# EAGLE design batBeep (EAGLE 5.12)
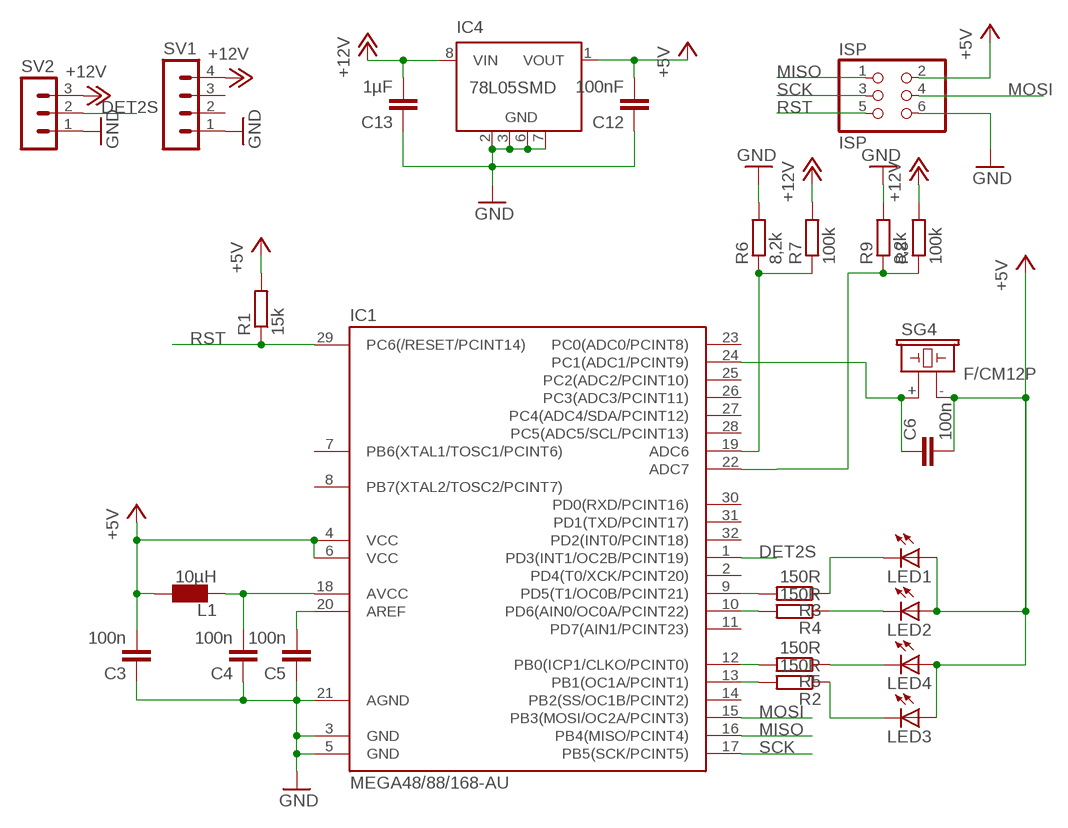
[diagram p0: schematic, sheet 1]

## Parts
C3  100n  C-EUC0402  [C0402]
C4  100n  C-EUC0402  [C0402]
C5  100n  C-EUC0402  [C0402]
C6  100n  C-EUC0402  [C0402]
C12  100nF  CAP0402-CAP  [0402-CAP]
C13  1µF  CAP0805  [0805]
IC1  MEGA48/88/168-AU  [TQFP32-08]
IC4  78L05SMD  [SO08]
ISP  ISP  PINHD-2X03_2.54  [2X03]
L1  10µH  L0805  [0805]
LED1  LEDCHIPLED_0805  [CHIPLED_0805]
LED2  LEDCHIPLED_0805  [CHIPLED_0805]
LED3  LEDCHIPLED_0805  [CHIPLED_0805]
LED4  LEDCHIPLED_0805  [CHIPLED_0805]
R1  15k  R-EU_R0402  [R0402]
R2  150R  R-EU_R0402  [R0402]
R3  150R  R-EU_R0402  [R0402]
R4  150R  R-EU_R0402  [R0402]
R5  150R  R-EU_R0402  [R0402]
R6  8,2k  R-EU_R0402  [R0402]
R7  100k  R-EU_R0402  [R0402]
R8  100k  R-EU_R0402  [R0402]
R9  8,2k  R-EU_R0402  [R0402]
SG4  F/CM12P  [F/CM12P]
SV1  MA04-1  [MA04-1]
SV2  MA03-1  [MA03-1]

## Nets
+5V: C3.2 C6.2 C12.2 IC1.4(VCC) IC1.6(VCC) IC4.1(VOUT) ISP.2 L1.1 LED1.A LED2.A LED3.A LED4.A R1.2 SG4.-
+12V: C13.2 IC4.8(VIN) R7.2 R8.2 SV1.4 SV2.3
AREF: C5.2 IC1.20(AREF)
AVCC: C4.2 IC1.18(AVCC) L1.2
DET2S: IC1.1(PD3(INT1/OC2B/PCINT19)) SV2.2
GND: C3.1 C4.1 C5.1 C12.1 C13.1 IC1.3(GND) IC1.5(GND) IC1.21(AGND) IC4.2(GND) IC4.3(GND) IC4.6(GND) IC4.7(GND) ISP.6 R6.2 R9.2 SV1.1 SV2.1
MISO: IC1.16(PB4(MISO/PCINT4)) ISP.1
MOSI: IC1.15(PB3(MOSI/OC2A/PCINT3)) ISP.4
N$1: C6.1 IC1.24(PC1(ADC1/PCINT9)) SG4.+
N$2: IC1.9(PD5(T1/OC0B/PCINT21)) R3.2
N$3: IC1.10(PD6(AIN0/OC0A/PCINT22)) R4.2
N$4: IC1.22(ADC7) R8.1 R9.1
N$6: IC1.12(PB0(ICP1/CLKO/PCINT0)) R5.2
N$7: IC1.13(PB1(OC1A/PCINT1)) R2.2
N$8: LED3.C R2.1
N$9: LED4.C R5.1
N$13: LED1.C R3.1
N$14: LED2.C R4.1
N$16: IC1.19(ADC6) R6.1 R7.1
RST: IC1.29(PC6(/RESET/PCINT14)) ISP.5 R1.1
SCK: IC1.17(PB5(SCK/PCINT5)) ISP.3
Unconnected: IC1.2(PD4(T0/XCK/PCINT20)) IC1.7(PB6(XTAL1/TOSC1/PCINT6)) IC1.8(PB7(XTAL2/TOSC2/PCINT7)) IC1.11(PD7(AIN1/PCINT23)) IC1.14(PB2(SS/OC1B/PCINT2)) IC1.23(PC0(ADC0/PCINT8)) IC1.25(PC2(ADC2/PCINT10)) IC1.26(PC3(ADC3/PCINT11)) IC1.27(PC4(ADC4/SDA/PCINT12)) IC1.28(PC5(ADC5/SCL/PCINT13)) IC1.30(PD0(RXD/PCINT16)) IC1.31(PD1(TXD/PCINT17)) IC1.32(PD2(INT0/PCINT18)) IC4.4(NC) IC4.5(NC) SV1.2 SV1.3

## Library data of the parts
C3-C6 = rcl:C-EU: CAPACITOR, European symbol
C12 C13 = SparkFun:CAP: Capacitor
IC1 = avr-7:MEGA48/88/168
IC4 = linear:78L*SMD: Positive VOLTAGE REGULATOR
ISP = pinhead-2:PINHD-2X03: PIN HEADER
L1 = seb:L0805
LED1-LED4 = led:LED: LED
R1-R9 = rcl:R-EU_: RESISTOR, European symbol
SG4 = buzzer:F/CM12P: BUZZER; OC_FARNELL: unknown; OC_NEWARK: unknown
SV1 = con-lstb:MA04-1: PIN HEADER; OC_FARNELL: unknown; OC_NEWARK: unknown
SV2 = con-lstb:MA03-1: PIN HEADER; OC_FARNELL: unknown; OC_NEWARK: unknown

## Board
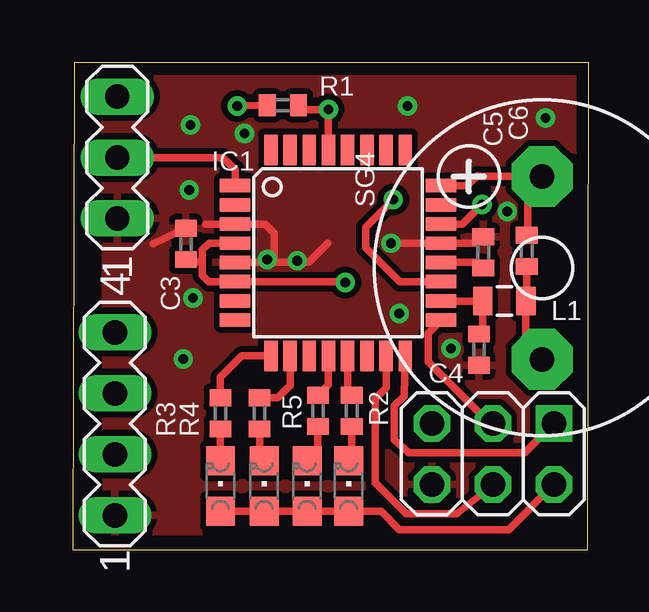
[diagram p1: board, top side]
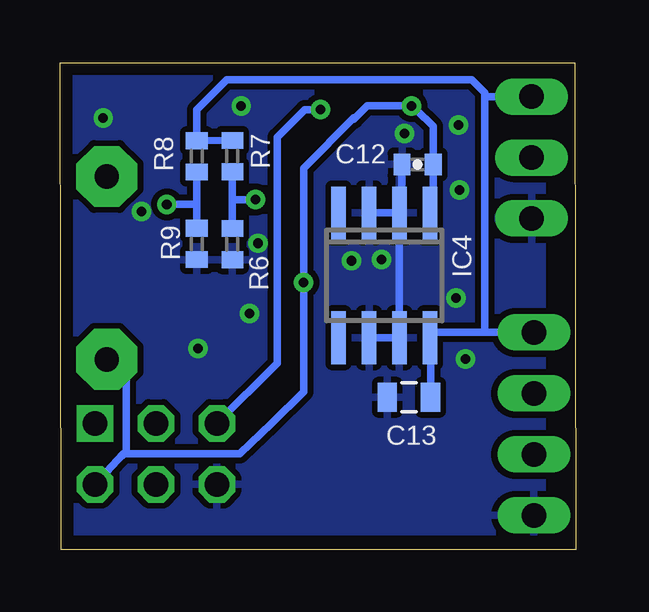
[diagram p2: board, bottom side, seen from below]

Size 21.5 x 20.3 mm. Coordinates in mm from the lower left corner, seen from the top.
Outline: 0,0 21.45,0 21.5,20.3 0.05,20.3 0,0
Copper layers (1*16): Top 0.035mm / dielectric 1.5mm / Bottom 0.035mm
Design rules "default *": minimum track width 10mil, minimum drill 24mil, track to track 8mil, track to pad 8mil, pad to pad 8mil, via to via 8mil, smd to smd 8mil, copper to edge 20mil, drill to drill 8mil, minimum pad ring 10mil, minimum via ring 8mil, stop-mask expansion 4mil, vias tented up to drill 30mil, thermal gap 10mil

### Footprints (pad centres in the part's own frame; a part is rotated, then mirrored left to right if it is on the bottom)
C0402 = smd 0.7 x 0.9: 1 -0.65,0; 2 0.65,0
0402-CAP = smd 0.7 x 0.9: 1 -0.65,0; 2 0.65,0
0805 = smd 0.8 x 1.2: 1 -0.9,0; 2 0.9,0
TQFP32-08 = smd 1.27 x 0.559: 1 -4.293,2.8; 2 -4.293,2; 3 -4.293,1.2; 4 -4.293,0.4; 5 -4.293,-0.4; 6 -4.293,-1.2; 7 -4.293,-2; 8 -4.293,-2.8; 17 4.293,-2.8; 18 4.293,-2; 19 4.293,-1.2; 20 4.293,-0.4; 21 4.293,0.4; 22 4.293,1.2; 23 4.293,2; 24 4.293,2.8 | smd 0.559 x 1.27: 9 -2.8,-4.293; 10 -2,-4.293; 11 -1.2,-4.293; 12 -0.4,-4.293; 13 0.4,-4.293; 14 1.2,-4.293; 15 2,-4.293; 16 2.8,-4.293; 25 2.8,4.293; 26 2,4.293; 27 1.2,4.293; 28 0.4,4.293; 29 -0.4,4.293; 30 -1.2,4.293; 31 -2,4.293; 32 -2.8,4.293
SO08 = smd 0.6 x 2.2: 1 -1.905,-2.6; 2 -0.635,-2.6; 3 0.635,-2.6; 4 1.905,-2.6; 5 1.905,2.6; 6 0.635,2.6; 7 -0.635,2.6; 8 -1.905,2.6
2X03 = drill 1.016 square: 1 -2.54,-1.27 | drill 1.016 octagon: 2 -2.54,1.27; 3 0,-1.27; 4 0,1.27; 5 2.54,-1.27; 6 2.54,1.27
CHIPLED_0805 = smd 1.2 x 1.2: A 0,-1.05; C 0,1.05
R0402 = smd 0.7 x 0.9: 1 -0.65,0; 2 0.65,0
F/CM12P = drill 1.016 pad 2.54 octagon: + 3.81,0; - -3.81,0
MA04-1 = drill 1.016 long: 1 -3.81,0; 2 -1.27,0; 3 1.27,0; 4 3.81,0
MA03-1 = drill 1.016 long: 1 -2.54,0; 2 0,0; 3 2.54,0

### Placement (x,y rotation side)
C3  4.71,12.75 270 top
C4  16.92,8.35 90 top
C5  17.1,12.4 270 top
C6  18.91,12.46 270 top
C12  6.6,16.06 0 bottom
C13  6.96,6.36 0 bottom
IC1  11.05,12.38 0 top
IC4  7.99,11.44 180 bottom
ISP  17.5,4 180 top
L1  17.98,10.37 180 top
LED1  6.15,2.66 0 top
LED2  7.97,2.66 0 top
LED3  11.49,2.66 0 top
LED4  9.76,2.66 0 top
R1  8.75,18.53 180 top
R2  11.62,5.79 90 top
R3  6.15,5.69 90 top
R4  7.78,5.69 90 top
R5  10.21,5.79 90 top
R6  14.32,12.74 270 bottom
R7  14.32,16.41 90 bottom
R8  15.8,16.4 90 bottom
R9  15.8,12.75 270 bottom
SG4  19.55,11.75 90 top
SV1  1.75,5.25 90 top
SV2  1.85,16.35 90 top

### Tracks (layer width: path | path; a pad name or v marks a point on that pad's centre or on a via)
+5V  (via drill 0.4)
  Top 0.305: 5.4,12 5.4,11.45 5.67,11.18 IC1.6 11.32,11.18 v11.35,11.15 | 5.4,12 5.4,12.5 5.68,12.78 IC1.4 | C3.2 4.66,12 5.4,12 | v6.85,18.5 R1.2 | LED1.A LED2.A LED4.A LED3.A 12.84,1.61 13.6,0.85 18.16,0.85 ISP.2 | SG4.- 18.88,7.94 18.88,8.61 L1.1 18.91,10.4 C6.2
  Bottom 0.305: 18.75,4 14,4 12.68,5.27 11.35,6.6 v11.35,11.15 11.35,15.9 9.25,18 9.25,17.95 8.7,18.5 v6.85,18.5 6.65,18.35 5.95,17.65 C12.2 5.95,14.17 IC4.1 | ISP.2 18.87,4 | 18.87,4 18.9,3.92 | 18.87,4 18.75,4 | 18.75,4 18.75,7.14 18.75,7.94 SG4.-
+12V
  Bottom 0.305: C13.2 6.06,8.81 IC4.8 5.86,9.06 3.75,9.06 | 3.8,19 3.8,9.71 3.8,9.11 3.75,9.06 | 3.8,19 3.8,19.05 4.35,19.6 14.55,19.6 15.7,18.45 15.8,18.35 R8.2 15.69,17.05 R7.2 | SV2.3 3.69,18.89 3.8,19 | SV1.4 3.75,9.06
AREF
  Top 0.305: IC1.20 16.87,11.98 C5.2
AVCC
  Top 0.305: IC1.18 15.35,10.37 L1.2 17.08,9.01 C4.2
DET2S
  Top 0.305: IC1.1 6.76,15.84 6.45,16.15 6.25,16.35 SV2.2
GND  (via drill 0.4)
  Top 0.305: IC1.5 8.4,11.98 | 8.4,11.98 9.83,11.98 10.63,12.78 | v13.25,12.78 IC1.21 16.83,12.78 C5.1 | 8.4,11.98 8.4,13.2 8.02,13.58 IC1.3 5.53,13.58 | 3.35,12.75 C3.1
  Bottom 0.305: IC4.2 IC4.3 | IC4.6 IC4.7 IC4.2 | IC4.2 7.25,14.14 C12.1
  other vias: 15.75,8.4 9.35,12.05 8.1,12.1 7.15,17.35 13.6,9.85 18.1,14.1 5,10.5 4.85,15 4.9,17.7 13.95,18.5 19.7,18 4.6,7.95
  pour Bottom (isolate 0.254): 1.4,0.75 21.4,0.75 21.4,20.2 1.4,20.2
  pour Top (isolate 0.254): 1.4,0.75 21.4,0.75 21.3,20.2 1.3,20.2
MISO
  Top 0.305: ISP.1 18.82,4.05 14,4.05 13.4,4.6 13.4,6 13.8,6.4 IC1.16
MOSI
  Top 0.305: IC1.15 13.05,6.75 12.6,6.3 12.6,2.8 13.9,1.5 16,1.5 17.28,2.53 ISP.4
N$1
  Top 0.305: C6.1 18.95,13.15 18.95,14.96 SG4.+ 16.89,15.56 16.85,15.6 16.43,15.18 IC1.24
N$2
  Top 0.305: R3.2 6.15,7.2 6.85,7.9 7.04,8.09 IC1.9
N$3
  Top 0.305: R4.2 8.54,6.34 8.95,6.75 9.05,6.85 IC1.10
N$4  (via drill 0.4)
  Top 0.305: v17.05,14.4 16.45,13.8 16.23,13.58 IC1.22
  Bottom 0.305: R8.1 R9.1 15.8,14.4 v17.05,14.4
N$6
  Top 0.305: R5.2 10.65,6.88 IC1.12
N$7
  Top 0.305: R2.2 11.45,6.61 IC1.13
N$8
  Top 0.305: LED3.C 11.62,3.84 R2.1
N$9
  Top 0.305: LED4.C 10.21,4.16 R5.1
N$13
  Top 0.305: R3.1 LED1.C
N$14
  Top 0.305: LED2.C 7.78,3.9 R4.1
N$16  (via drill 0.4)
  Top 0.305: IC1.19 13.62,11.18 12.2,12.6 12.2,13.45 v13.35,14.6
  Bottom 0.305: v13.35,14.6 13.9,14.6 14.27,14.6 14.32,14.55 | 14.32,14.55 R6.1 | 14.32,14.55 R7.1
RST  (via drill 0.4)
  Top 0.305: IC1.29 v10.65,18.35 9.58,18.35 R1.1
  Bottom 0.305: ISP.5 12.45,7.78 12.45,17.2 11.3,18.35 v10.65,18.35
SCK
  Top 0.305: ISP.3 17.33,5.32 14.8,7.85 14.8,9.04 IC1.17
